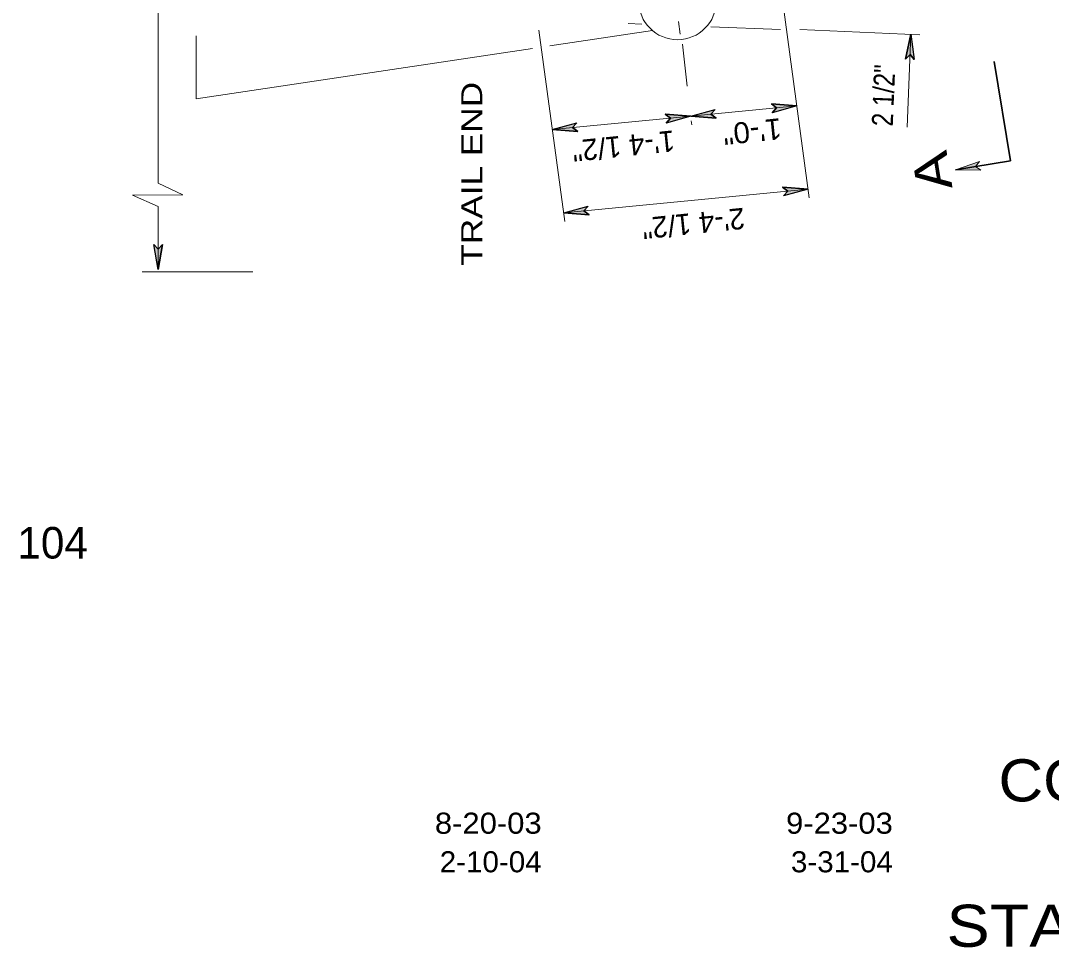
# Model space of a CAD drawing. Extents: x 12.6 to 19.5, y 6.1 to 16.3.
# Drawn here: x 12.578 to 15.515, y 6.055 to 8.696 of the extents above; entities that cross this region are included whole.
import ezdxf
from ezdxf.enums import TextEntityAlignment as Align

# ---------------------------------------------------------------- set-up
doc = ezdxf.new("R2010")
doc.units = 0
doc.header["$LTSCALE"] = 0.024
doc.linetypes.add('DOT_DASHED', pattern=[7.7, 5, -1.2, 0.3, -1.2])
for name, color, linetype, lineweight in [('1', 7, 'Continuous', 35), ('10', 7, 'Continuous', 25), ('12', 7, 'Continuous', 53), ('13', 7, 'Continuous', 53)]:
    doc.layers.add(name, color=color, linetype=linetype, lineweight=lineweight)

msp = doc.modelspace()

# ---------------------------------------------------------------- hatches: boundary and pattern name
at = {"layer": '10'}
for points in [[(15.0994, 8.5864), (15.115, 8.6573), (15.1246, 8.5853), (15.1125, 8.5994)], [(14.7173, 8.459), (14.7897, 8.4535), (14.7198, 8.434), (14.732, 8.4478)], [(14.4152, 8.4294), (14.4876, 8.4237), (14.4176, 8.4043), (14.4299, 8.4182)], [(14.56, 8.4181), (14.4876, 8.4236), (14.5575, 8.4431), (14.5453, 8.4293)], [(14.1657, 8.3803), (14.0933, 8.386), (14.1633, 8.4054), (14.151, 8.3915)], [(15.3142, 8.2703), (15.2416, 8.2712), (15.3101, 8.2952), (15.2988, 8.2805)], [(14.7495, 8.2217), (14.8219, 8.2161), (14.752, 8.1966), (14.7642, 8.2105)], [(14.198, 8.1428), (14.1256, 8.1484), (14.1955, 8.1679), (14.1833, 8.154)], [(12.9831, 8.0581), (12.9705, 7.9866), (12.9579, 8.0581), (12.9705, 8.0446)]]:
    msp.add_hatch(color=256, dxfattribs=at).paths.add_polyline_path(points)

# ---------------------------------------------------------------- linework, layer by layer
at = {"layer": '10', "lineweight": 13}
for p, q in [((12.9705, 8.2335), (12.9705, 9.1269)), ((14.7507, 8.7412), (14.8253, 8.1913)), ((14.0548, 8.6696), (14.1289, 8.1236)), ((14.0862, 8.6241), (14.379, 8.6678)), ((14.3486, 8.6866), (14.3092, 8.6883)), ((14.7432, 8.6706), (14.5452, 8.679)), ((14.7984, 8.6707), (15.1399, 8.6563)), ((13.0785, 8.6529), (13.0785, 8.4739)), ((15.115, 8.6573), (15.1038, 8.3931)), ((13.0785, 8.4739), (14.0368, 8.6168)), ((14.4876, 8.4236), (14.7897, 8.4535)), ((14.4876, 8.4237), (14.0933, 8.386)), ((15.2416, 8.2712), (15.3101, 8.2952)), ((15.2416, 8.2712), (15.3142, 8.2703)), ((14.1256, 8.1484), (14.8219, 8.2161)), ((12.9705, 7.9866), (12.9705, 8.1669)), ((13.24, 7.9801), (12.9251, 7.9801))]:
    msp.add_line(p, q, dxfattribs=at)
at = {"layer": '10', "linetype": 'DOT_DASHED', "lineweight": 13}
for p, q in [((14.4531, 8.6937), (14.4577, 8.658)), ((14.4638, 8.6289), (14.4905, 8.3989))]:
    msp.add_line(p, q, dxfattribs=at)
at = {"layer": '10'}
for p, q in [((15.115, 8.6573), (15.0994, 8.5864)), ((15.115, 8.6573), (15.1246, 8.5853)), ((14.7897, 8.4535), (14.7173, 8.459)), ((14.4876, 8.4237), (14.4152, 8.4294)), ((14.4876, 8.4236), (14.5575, 8.4431)), ((14.7897, 8.4535), (14.7198, 8.434)), ((14.0933, 8.386), (14.1633, 8.4054)), ((14.4876, 8.4237), (14.4176, 8.4043)), ((14.4876, 8.4236), (14.56, 8.4181)), ((14.0933, 8.386), (14.1657, 8.3803)), ((14.8219, 8.2161), (14.7495, 8.2217)), ((14.8219, 8.2161), (14.752, 8.1966)), ((14.1256, 8.1484), (14.1955, 8.1679)), ((14.1256, 8.1484), (14.198, 8.1428)), ((12.9705, 7.9866), (12.9579, 8.0581)), ((12.9705, 7.9866), (12.9831, 8.0581))]:
    msp.add_line(p, q, dxfattribs=at)
at = {"layer": '10', "lineweight": 35}
for q in [(15.3522, 8.58), (15.2416, 8.2712)]:
    msp.add_line((15.3984, 8.2968), q, dxfattribs=at)
at = {"layer": '10'}
for points in [[(15.0994, 8.5864), (15.115, 8.6573), (15.1246, 8.5853), (15.1125, 8.5994)], [(14.7173, 8.459), (14.7897, 8.4535), (14.7198, 8.434), (14.732, 8.4478)], [(14.4152, 8.4294), (14.4876, 8.4237), (14.4176, 8.4043), (14.4299, 8.4182)], [(14.56, 8.4181), (14.4876, 8.4236), (14.5575, 8.4431), (14.5453, 8.4293)], [(14.1657, 8.3803), (14.0933, 8.386), (14.1633, 8.4054), (14.151, 8.3915)], [(14.7495, 8.2217), (14.8219, 8.2161), (14.752, 8.1966), (14.7642, 8.2105)], [(14.198, 8.1428), (14.1256, 8.1484), (14.1955, 8.1679), (14.1833, 8.154)], [(12.9831, 8.0581), (12.9705, 7.9866), (12.9579, 8.0581), (12.9705, 8.0446)]]:
    msp.add_lwpolyline(points, close=True, dxfattribs=at)
for points in [[(15.0994, 8.5864), (15.1125, 8.5994), (15.1246, 8.5853)], [(14.7173, 8.459), (14.732, 8.4478), (14.7198, 8.434)], [(14.4152, 8.4294), (14.4299, 8.4182), (14.4176, 8.4043)], [(14.56, 8.4181), (14.5453, 8.4293), (14.5575, 8.4431)], [(14.1657, 8.3803), (14.151, 8.3915), (14.1633, 8.4054)], [(14.7495, 8.2217), (14.7642, 8.2105), (14.752, 8.1966)], [(14.198, 8.1428), (14.1833, 8.154), (14.1955, 8.1679)], [(12.9831, 8.0581), (12.9705, 8.0446), (12.9579, 8.0581)]]:
    msp.add_lwpolyline(points, dxfattribs=at)
at = {"layer": '10', "lineweight": 13}
msp.add_lwpolyline([(15.3142, 8.2703), (15.2416, 8.2712), (15.3101, 8.2952), (15.2988, 8.2805)], close=True, dxfattribs=at)
for points in [[(15.3142, 8.2703), (15.2988, 8.2805), (15.3101, 8.2952)], [(12.9705, 8.1669), (12.897, 8.1991), (13.0407, 8.2002), (12.9705, 8.2335)]]:
    msp.add_lwpolyline(points, dxfattribs=at)
msp.add_circle((14.44991, 8.75269), 0.11072, dxfattribs=at)

# ---------------------------------------------------------------- texts
at = {"layer": '1'}
for s, width, p in [('8-20-03', 1.1, (14.0629, 6.3788)), ('9-23-03', 1.1, (15.0634, 6.3788)), ('2-10-04', 1.05, (14.0629, 6.2688)), ('3-31-04', 1.05, (15.0634, 6.2688))]:
    msp.add_text(s, height=0.06, dxfattribs=dict(at, width=width)).set_placement(p, align=Align.RIGHT)
at = {"layer": '12'}
for s, height, rotation, width, p in [('2 1/2"', 0.06, 87.58, 0.85, (15.0631, 8.394)), ('1\'-0"', 0.06, 185.877, 1.05, (14.7434, 8.4186)), ('A', 0.1, 99.255, 1.25, (15.2335, 8.2197))]:
    msp.add_text(s, height=height, rotation=rotation, dxfattribs=dict(at, width=width)).set_placement(p)
at = {"layer": '12', "width": 1.25}
msp.add_text('TRAIL END', height=0.06, rotation=90, dxfattribs=at).set_placement((13.8936, 8.5217), align=Align.RIGHT)
at = {"layer": '12'}
for s, p in [('1\'-4 1/2"', (14.4392, 8.3839)), ('2\'-4 1/2"', (14.6384, 8.1632))]:
    msp.add_text(s, height=0.06, rotation=185.877, dxfattribs=at).set_placement(p)
at = {"layer": '13'}
msp.add_text('104', height=0.09, dxfattribs=at).set_placement((12.6697, 7.1631), align=Align.CENTER)
for s, width, p in [('CONCRETE TRAFFIC BARRIER TERMINAL END-', 1.1, (17.3845, 6.4709)), ('STANDARD NO.', 1.15, (15.9135, 6.0565))]:
    msp.add_text(s, height=0.12, dxfattribs=dict(at, width=width)).set_placement(p, align=Align.CENTER)

doc.saveas('drawing.dxf')
